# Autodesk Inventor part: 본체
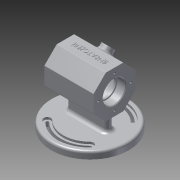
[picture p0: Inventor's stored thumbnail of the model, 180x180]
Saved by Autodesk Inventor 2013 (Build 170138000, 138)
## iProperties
Created: 2017-04
Part Number: 본체
Material: 알루미늄 6061
Document SubType Name: Modeling
Designer: Administrator
Density: 2.71 g/cm^3
Mass: 588.175 g
Surface Area: 574.36 cm^2
Volume: 217.039 cm^3
Author: Administrator
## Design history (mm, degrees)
sketch "스케치1"
  geometry: C1 r 55 at (0, 0); 1 further point
  constraints: 1 centre point, 1 coincident
  dimensions: "d0" = 110 diameter of C1
extrude "돌출1" new body sketch "스케치1" distance "d2" = 10; taper "d3" = 0 deg
sketch "스케치2"
  geometry: L1 (0, 0)-(0, 48); L2 (-48.451, 0)-(48.451, 0); L3 (0, 0)-(-33.941, 33.941); L4 (0, 0)-(33.941, 33.941); L5 (-33.941, 33.941)-(-26.87, 26.87); L6 (26.87, 26.87)-(33.941, 33.941); A1 r 48 centre (0, 0) between (33.941, 33.941) and (-33.941, 33.941); A2 r 38 centre (0, 0) between (26.87, 26.87) and (-26.87, 26.87); 3 further points
  constraints: 12 end point, 7 point on circle, 4 point on line, 3 coincident, 2 centre point, 2 perpendicular, 1 midpoint, 1 vertical, 10 other
  dimensions: "d6" = 45 deg angle of L1 L3; "d7" = 48 radius of A1; "d9" = 38 radius of A2
extrude "돌출2" cut sketch "스케치2" distance "d10" = 3; taper "d11" = 0 deg
sketch "스케치9"
  geometry: A1 r 48 centre (0, 0) between (33.941, 33.941) and (-33.941, 33.941) reference; A2 r 5 centre (-30.406, 30.406) between (-33.941, 33.941) and (-26.87, 26.87) reference; A3 r 38 centre (0, 0) between (26.87, 26.87) and (-26.87, 26.87) reference; A4 r 5 centre (30.406, 30.406) between (26.87, 26.87) and (33.941, 33.941) reference; A5 r 45 centre (0, 0) between (31.82, 31.82) and (-31.82, 31.82); A6 r 2 centre (30.406, 30.406) between (28.991, 28.991) and (31.82, 31.82); A7 r 41 centre (0, 0) between (28.991, 28.991) and (-28.991, 28.991); A8 r 2 centre (-30.406, 30.406) between (-31.82, 31.82) and (-28.991, 28.991); 1 further point
  constraints: 8 point on circle, 4 centre point, 3 other
  dimensions: "d62" = 2 radius of A8
extrude "돌출7" cut sketch "스케치9" distance "d64" = 7; taper "d65" = 0 deg
sketch "스케치3"
  geometry: L1 (35, 78)-(23, 78); L2 (23, 78)-(23, 76); L3 (23, 76)-(20, 76); L4 (20, 76)-(20, 87); L5 (20, 87)-(-20, 87); L6 (-20, 87)-(-20, 76); L7 (-20, 76)-(-23, 76); L8 (-23, 76)-(-23, 78); L9 (-23, 78)-(-35, 78); L10 (-35, 78)-(-35, 92); L11 (-35, 92)-(35, 92); L12 (35, 92)-(35, 78); L13 (-35, 62)-(35, 62); 2 further points
  constraints: 26 end point, 9 parallel, 3 vertical alignment, 1 collinear, 1 horizontal, 1 midpoint, 1 perpendicular, 1 vertical
  dimensions: "d13" = 70 distance of L13.start L13.end; "d14" = 60 diameter of L11 L13; "d15" = 32 diameter of L9 L13; "d16" = 28 diameter of L7 L13; "d17" = 50 diameter of L5 L13; "d18" = 28 diameter of L3 L13; "d19" = 32 diameter of L1 L13; "d20" = 12 distance of L8.end L9.end; "d21" = 3 distance of L6.end L7.end; "d22" = 40 distance of L4.end L5.end; "d23" = 3 distance of L2.end L3.end; "d66" = 124 diameter of point (0, 0) L13
revolve "회전1" sketch "스케치3" stored, may be unused: angle "d24" = 90 deg
sketch "스케치4"
  geometry: L1 (12.426, 30)-(30, 12.426); L2 (30, 12.426)-(30, -12.426); L3 (30, -12.426)-(12.426, -30); L4 (12.426, -30)-(-12.426, -30); L5 (-12.426, -30)-(-30, -12.426); L6 (-30, -12.426)-(-30, 12.426); L7 (-30, 12.426)-(-12.426, 30); L8 (-12.426, 30)-(12.426, 30); 4 further points
  constraints: 16 end point, 2 vertical alignment, 1 coincident, 1 midpoint, 18 other
extrude "돌출3" join sketch "스케치4" distance "d25" = 70; taper "d26" = 0 deg
sketch "스케치5"
  geometry: L1 (-24, 5)-(24, 5); L2 (24, 5)-(24, -5); L3 (24, -5)-(-24, -5); L4 (-24, -5)-(-24, 5); L5 (24, -5)-(-24, 5); 4 further points
  constraints: 10 end point, 3 midpoint, 2 parallel, 2 vertical alignment, 1 coincident, 1 horizontal, 1 perpendicular, 4 other
  dimensions: "d27" = 48 distance of L1.start L1.end; "d29" = 10 distance of L1.end L2.end
extrude "돌출4" join sketch "스케치5" stored distance "d30" = 70; taper "d31" = 0 deg
fillet "모깎기1" dims "d32" = 5
chamfer "모따기2" distance "d57" = 1; stored, may be unused: second distance "d58" = 2, angle "d59" = 45 deg
fillet "모깎기2" dims "d60" = 0.3
fillet "모깎기3" dims "d61" = 3
fillet "모깎기4" dims "d67" = 3
sketch "스케치11"
  geometry: L1 (70, 0)-(70, 24.853) reference; C1 r 8 at (35, 12.426); 2 further points
  constraints: 1 centre point, 1 horizontal alignment, 1 midpoint, 1 vertical alignment
  dimensions: "d72" = 16 diameter of C1
extrude "돌출8" join sketch "스케치11" distance "d74" = 7; taper "d75" = 0 deg
fillet "모깎기7" dims "d76" = 3
sketch "스케치12"
  geometry: C1 r 8 at (0, 0) reference; C2 r 4 at (0, 0); 1 further point
  constraints: 1 centre point, 1 coincident
  dimensions: "d77" = 8 diameter of C2
extrude "돌출9" cut sketch "스케치12" stored distance "d79" = 7; taper "d80" = 0 deg
chamfer "모따기3" distance "d81" = 1; stored, may be unused: second distance "d82" = 2, angle "d83" = 45 deg
sketch "스케치13"
  geometry: L1 (0, 0)-(-70, 0); L2 (-70, 0)-(-70, 24.853); L3 (-70, 24.853)-(0, 24.853); L4 (0, 24.853)-(0, 0); L5 (0, 0)-(0, 24.853) reference; L6 (0, 24.853)-(-70, 24.853) reference; 2 further points
  constraints: 3 coincident, 2 collinear, 2 other
feature "엠보싱2" sketch "스케치13" dims "d2" = 10, "d3" = 0, "d13" = 70, "d14" = 60, "d15" = 32, "d16" = 28, "d17" = 50, "d18" = 28, "d19" = 32, "d20" = 12, "d21" = 3, "d22" = 40, "d23" = 3, "d66" = 124, "d84" = 0.5, "d85" = 0
sketch "스케치14" dims "d86" = 46
  geometry: L1 (0, 0)-(-17.574, -17.574) reference; L2 (0, 24.853)-(0, 0) reference; L3 (-17.574, 42.426)-(0, 24.853) reference; L4 (-42.426, 42.426)-(-17.574, 42.426) reference; L5 (-60, 24.853)-(-42.426, 42.426) reference; L6 (-60, 0)-(-60, 24.853) reference; L7 (-42.426, -17.574)-(-60, 0) reference; L8 (-17.574, -17.574)-(-42.426, -17.574) reference; C1 r 17 at (-30, 12.426) reference; 3 further points
  constraints: 2 vertical alignment, 1 coincident, 2 other
hole "구멍2" sketch "스케치14" at (-30, 35.426) diameter "d88" = 3.242; stored, may be unused: countersink angle "d92" = 82 deg, drill point angle "d94" = 118 deg; dims "d89" = 8, "d90" = 3.023, "d91" = 2, "d93" = 10
fillet "모깎기8" dims "d98" = 1
node "솔리드1"
mirror "대칭1"
pattern_circular "원형 패턴2" dims angle "d96" = 360 deg
mirror "대칭3"
node "투영된 루프3"
node "투영된 루프4"
node "투영된 루프5"
other parameters: "d4" = 96, "d5" = 76
